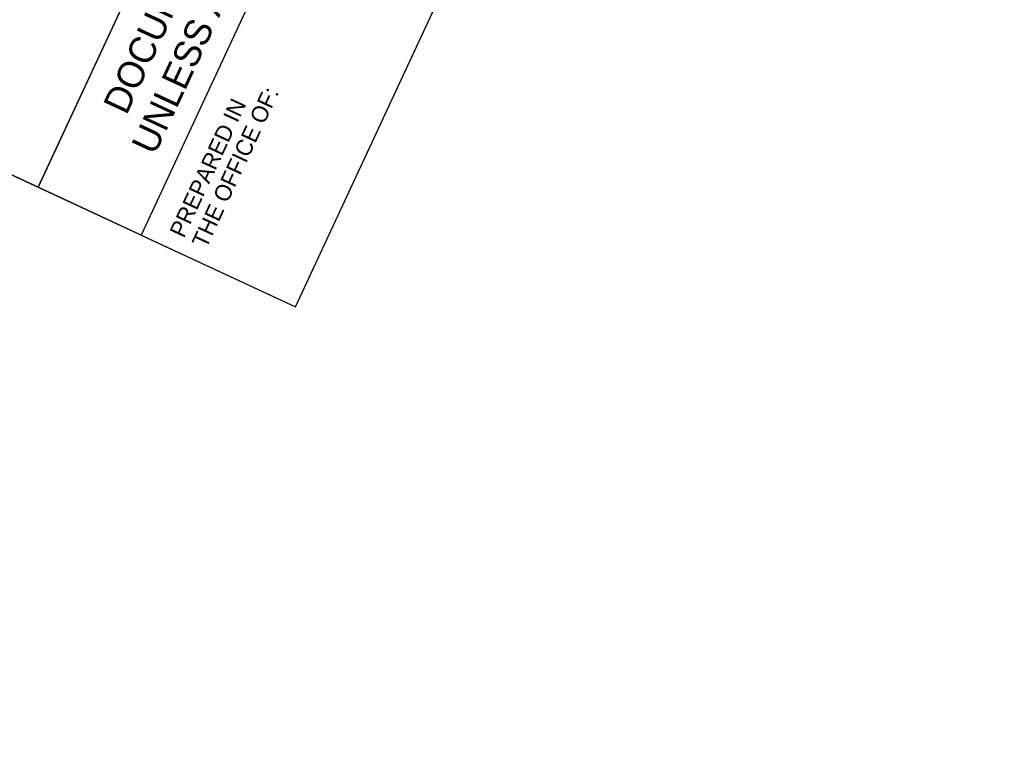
# Model space of a CAD drawing. Extents: x 2532214 to 2534758, y 714172 to 717266.
# Drawn here: x 2532985.3 to 2533186.5, y 716233.1 to 716384.7 of the extents above; entities that cross this region are included whole.
import ezdxf

# ---------------------------------------------------------------- set-up
doc = ezdxf.new("R2010")
doc.units = 0
for name, color, linetype in [('Dimension Lines CELL', 7, 'Continuous'), ('Mis Center Lines', 7, 'Continuous'), ('Structural Steel Angle 3 x 3', 7, 'Continuous'), ('Structural Steel Angle 3 x 3 Hidden', 7, 'Continuous'), ('Structural Steel Lines', 7, 'Continuous'), ('Text', 7, 'Continuous')]:
    doc.layers.add(name, color=color, linetype=linetype)

msp = doc.modelspace()

# ---------------------------------------------------------------- linework, layer by layer
at = {"layer": 'Dimension Lines CELL'}
msp.add_lwpolyline([(2533392.43, 716327.91), (2533206.82, 715928.98), (2532801.87, 715058.57), (2532325.86, 715280.03), (2532853.13, 716413.33), (2533042.37, 716325.28), (2533105.67, 716461.33), (2533324.42, 716359.55)], close=True, dxfattribs=at)
at = {"layer": 'Mis Center Lines'}
for p, q in [((2532989.17, 716350.03), (2533073.55, 716531.4)), ((2533094.86, 716521.49), (2533010.48, 716340.12)), ((2533010.48, 716340.12), (2532989.17, 716350.03))]:
    msp.add_line(p, q, dxfattribs=at)
at = {"layer": 'Structural Steel Angle 3 x 3'}
msp.add_lwpolyline([(2532325.86, 715280.03), (2532853.13, 716413.33), (2533042.37, 716325.28), (2533126.76, 716506.66), (2533345.52, 716404.88), (2533138.82, 715960.61), (2533229.49, 715918.43), (2532824.53, 715048.02)], close=True, dxfattribs=at)
at = {"layer": 'Structural Steel Angle 3 x 3 Hidden'}
msp.add_lwpolyline([(2533094.86, 716521.49), (2533010.48, 716340.12), (2533042.37, 716325.28), (2533126.75, 716506.65)], close=True, dxfattribs=at)
at = {"layer": 'Structural Steel Lines'}
msp.add_lwpolyline([(2532887.17, 716397.49), (2532929.37, 716488.2), (2533031.38, 716440.74), (2532989.17, 716350.03)], close=True, dxfattribs=at)

# ---------------------------------------------------------------- texts
at = {"layer": 'Mis Center Lines'}
for s, p in [('DOCUMENT NOT CONSIDERED FINAL', (2533007.44, 716364.77)), ('UNLESS ALL SIGNATURES COMPLETED', (2533013.28, 716356.46))]:
    msp.add_text(s, height=5.5, rotation=65.05, dxfattribs=at).set_placement(p)
at = {"layer": 'Text'}
for s, p in [('THE OFFICE OF:', (2533023.92, 716337.19)), ('PREPARED IN ', (2533019.29, 716339.34))]:
    msp.add_text(s, height=3.4, rotation=65.05, dxfattribs=at).set_placement(p)

doc.saveas('drawing.dxf')
